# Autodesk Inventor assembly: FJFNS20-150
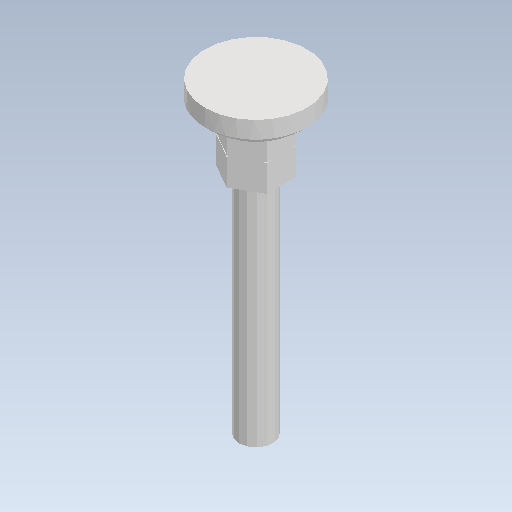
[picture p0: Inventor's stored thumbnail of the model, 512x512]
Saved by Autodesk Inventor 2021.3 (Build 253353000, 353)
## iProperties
Created: 2022-02
Part Number: FJFNS20-150
Document SubType Name: Assembly
Designer: kengo
Author: kengo
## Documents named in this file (4)
- C:\Users\kengo\Documents\S2S_frame\SDC345\frame_misumi_ver12\FJFNS20-150.iam
- C:\Users\kengo\Documents\S2S_frame\SDC345\frame_misumi_ver12\FJFNS20-150-PART1.ipt
- C:\Users\kengo\Documents\S2S_frame\SDC345\frame_misumi_ver12\FJFNS20-150-PART2.ipt
- C:\Users\kengo\Documents\S2S_frame\SDC345\frame_misumi_ver12\FJFNS20-150-PART3.ipt
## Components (3 placed, 3 different names)
1. FJFNS20-150-PART1
2. FJFNS20-150-PART2
3. FJFNS20-150-PART3
